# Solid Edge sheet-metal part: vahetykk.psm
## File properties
Author: Mac
Template: Normal.psm
Last saved by: Mac
Revision: 5
Application: Solid Edge
Density: 2712,000 kg/m^3
Accuracy: 0,990
Material Thickness: 0,06 mm
Bend Radius: 1,00 mm
Relief Width: 1,00 mm
Relief Length: 0,00 mm
Neutral Factor: 0,330
Minimum Arc Length: 0,10 mm
Deviational Tolerance: 0,10 mm
Material: Aluminum, 1060
Face Style: Aluminum
Fill Style: ANSI38(Aluminum)
Virtual Style: Brushed aluminum pattern
Coef. of Thermal Exp: 2.3e-05
Thermal Conductivity: 221.0
Specific Heat: 920.0
Modulus of Elasticity: 68947570000.0
Poission's Ratio: 0.33
Yield Stress: 27579028.0
Ultimate Stress: 68947570.0
Elongation: 0.0
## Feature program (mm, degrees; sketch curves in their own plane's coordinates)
base contour flange "ContourFlange_1"
flange "Flange_1"
insert bend "InsertBend_3"  BendAngle = 90 deg
body pattern "unnamed BodyPattern 1"
pattern "unnamed Pattern 1"
sheet metal cutout "unnamed SheetMetalCutout 1"
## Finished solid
Body 1: solid body, 50 faces, 124 edges, 72 vertices.
  Faces by surface: plane 34, cylinder 16
  Edges by curve: line 92, circle 32
Bounding box of the edges (mm): 1.400 x 27.035 x 0.872, from (-0.7, -0.9578, -0.072) to (0.7, 26.0778, 0.8).
Cylindrical faces by radius (mm): R0.002 x6, R0.062 x6, R0.0865 x4
Planar faces by outward normal: +x 6, +y 7, +z 5, -x 6, -y 7, -z 3
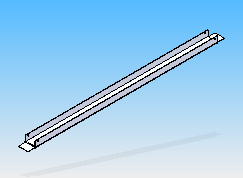
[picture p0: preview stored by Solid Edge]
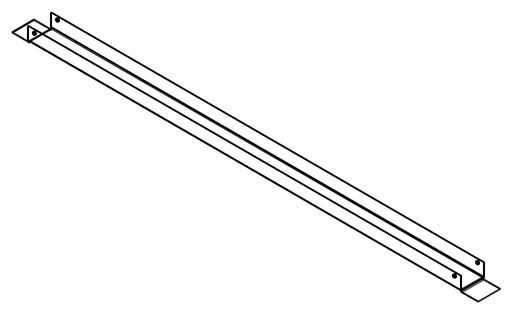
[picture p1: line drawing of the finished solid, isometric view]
